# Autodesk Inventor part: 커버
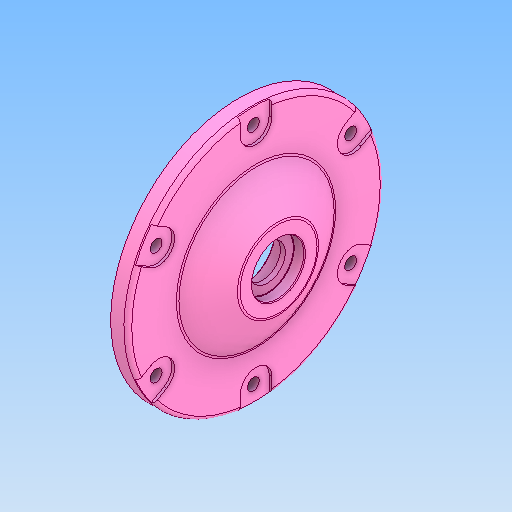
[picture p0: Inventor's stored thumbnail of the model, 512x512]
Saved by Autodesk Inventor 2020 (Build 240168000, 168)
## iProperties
Created: 2025-11
Part Number: 커버
Material: 알루미늄 6061
Document SubType Name: Modeling
Designer: PC2-06
Density: 2.7 g/cm^3
Appearance: 기본값
Author: jhkim
Sending System: Autodesk Inventor 2026
Preprocessor: ST-DEVELOPER v20.1
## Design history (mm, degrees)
feature "솔리드1"
node "솔리드2"
